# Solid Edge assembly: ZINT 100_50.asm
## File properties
Title: Zylinder
Author: bmolnar
Template: iso metric assembly.asm
Last saved by: bmolnar
Revision: 23
Application: Solid Edge
Username: bmolnar
Dokumentum tartalom típus: 1
Document Number: ZINT 100/50
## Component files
hrungsstange.par
Profilrohr.par
Platte.par
Kolbenstange.par
Kit_2.par
Kit_1.par
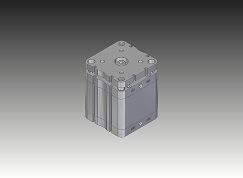
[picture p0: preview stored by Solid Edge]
